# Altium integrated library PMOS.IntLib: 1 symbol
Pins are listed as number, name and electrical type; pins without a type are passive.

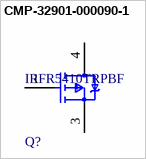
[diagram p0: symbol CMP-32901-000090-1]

## CMP-32901-000090-1
designator Q?, comment IRFR5410TRPBF
MOSFET P-CH 100V 13A DPAK; Manufacturer: Infineon; Threshold Vgs Min: -2V; Pulse Drain Current: -52A; Max Junction Temp: +150°C; Drain To Source Voltage: -100V; Max Forward Diode Voltage: -1.6V; Power Dissipation: 66W; Turn On Delay Time: 15ns; Input Capacitace At Vds: 760pF @ -25V; Rthja Max: 50°C/W; Depletion Mode: False; Number Of P Channels: 1; Reverse Recovery Time: 130ns; Continuous Drain Current: -13A; Drain To Source Resistance: 0.205Ω; Threshold Vgs Max: -4V; Reverse Recovery Charge: 650nC; Gate To Source Voltage: 20V; Gate Charge At Vgs: 58nC @ -10V; Turn Off Delay Time: 45ns
footprint FP-PG-TO252-3-MFG
pins: 1 G, 3 S, 4 D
